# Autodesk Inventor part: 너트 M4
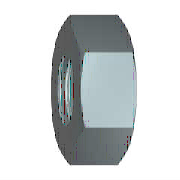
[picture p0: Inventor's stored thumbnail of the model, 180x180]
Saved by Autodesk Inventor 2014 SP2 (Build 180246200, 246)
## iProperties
Created: 2012-02
Part Number: 너트 M4
Material: 강철, 연강
Description: 6각 너트 및 6각 가는 너트 - 스타일 1
Document SubType Name: Modeling
Standard: KS B 1012
Designer: mduedu
Standards Organization: KS
Language: ko-KR
Size Designation: A M4
Categories: <MemberInstance><Categories><Category DisplayName="조임쇠" InternalName="e4da775c-781d-43d5-af7c-5136215cf5a6" Mnemonic="FSTN"><Category DisplayName="너트" InternalN
Density: 7.86 g/cm^3
Appearance: 강철
Mass: 0.846697 g
Surface Area: 1.71448 cm^2
Volume: 0.107722 cm^3
IsCustomPart: 0
Author: mduedu
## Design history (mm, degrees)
sketch "스케치1"
  geometry: L1 (-4.041, 0)-(-2.021, 3.5); L2 (-2.021, 3.5)-(2.021, 3.5); L3 (2.021, 3.5)-(4.041, 0); L4 (4.041, 0)-(2.021, -3.5); L5 (2.021, -3.5)-(-2.021, -3.5); L6 (-2.021, -3.5)-(-4.041, 0); 2 further points
  constraints: 12 end point, 1 coincident, 1 horizontal, 11 other
  dimensions: "d0" = 8.0829 distance of L3.end L1.start (= 1.1547 x SW)
extrude "본체" new body sketch "스케치1" distance "d1" = 3.2 (= KOH); taper "d2" = 0 deg
sketch "스케치2"
  geometry: L1 (0, 2.021)-(0, 4.041) reference; L2 (0, 4.041)-(3.2, 4.041) reference; L3 (3.2, 2.021)-(3.2, 4.041) reference; L4 (-0.64, 0)-(3.84, 0) reference; L5 (0.313, 4.041)-(0, 3.5); L6 (2.887, 4.041)-(3.2, 3.5)
  constraints: 4 end point, 4 point on line
  dimensions: "d3" = 30 deg angle of L1 L5 (= ANG1); "d4" = 30 deg angle of L3 L6 (= ANG2); "d5" = 7 diameter of L5.end L4 (= SW0); "d6" = 7 diameter of L6.end L4 (= SW01)
revolve "모따기1" sketch "스케치2" stored, may be unused: angle "d7" = 90 deg
sketch "스케치3"
  geometry: A1 r 3.5 centre (0, 0) between (-1.75, -3.031) and (1.75, -3.031) reference; 1 further point
  constraints: 1 coincident
hole "스레드" sketch "스케치3" at (0, 0) diameter "d25" = 3.242; stored, may be unused: countersink angle "d29" = 82 deg, drill point angle "d31" = 118 deg; dims "d26" = 6, "d27" = 4, "d28" = 2, "d30" = 8
workaxis "Work Axis1"
workplane "Work Plane1"
body "Solid1"
chamfer "모따기2" distance "d8" = 0.37889 (= -0.5 x GD1 + 0.5 x NND); stored, may be unused: angle "d9" = 30 deg, second distance "d40" = 0.37889 (= -0.5 x GD1 + 0.5 x NND)
chamfer "모따기3" distance "d10" = 0.37889 (= -0.5 x GD1 + 0.5 x NND); stored, may be unused: angle "d11" = 30 deg, second distance "d41" = 0.37889 (= -0.5 x GD1 + 0.5 x NND)
other parameters: "ANG1" = 30 deg [user parameter; used in 1 equation term], "ANG2" = 30 deg [user parameter; used in 1 equation term], "NND" = 4 [user parameter; used in 4 equation terms], "KOH" = 3.2 [user parameter; used in 1 equation term], "SW" = 7 [user parameter; used in 4 equation terms], "SW0" = 7 (= SW) [user parameter; used in 1 equation term], "SW01" = 7 (= SW) [user parameter; used in 1 equation term], "GD1" = 3.24223 (computed from THREADDIA, PTC, TOA) [user parameter; used in 4 equation terms], "d13" = 0, "d14" = 0, "d39" = 0, "d42" = 0, "GUL" = 0.37889 (= 0.541266 x PTC) [user parameter], "TPU" = 14.28571 (computed from PTC) [user parameter], "THREADDIA" = 4 [user parameter; used in 1 equation term], "TOA" = 30 deg [user parameter; used in 1 equation term], "PTC" = 0.7 [user parameter; used in 4 equation terms], "E0" = 8.085 (= 1.155 x SW) [user parameter], "GAL" = 0.37889 (= 0.541266 x PTC) [user parameter]
